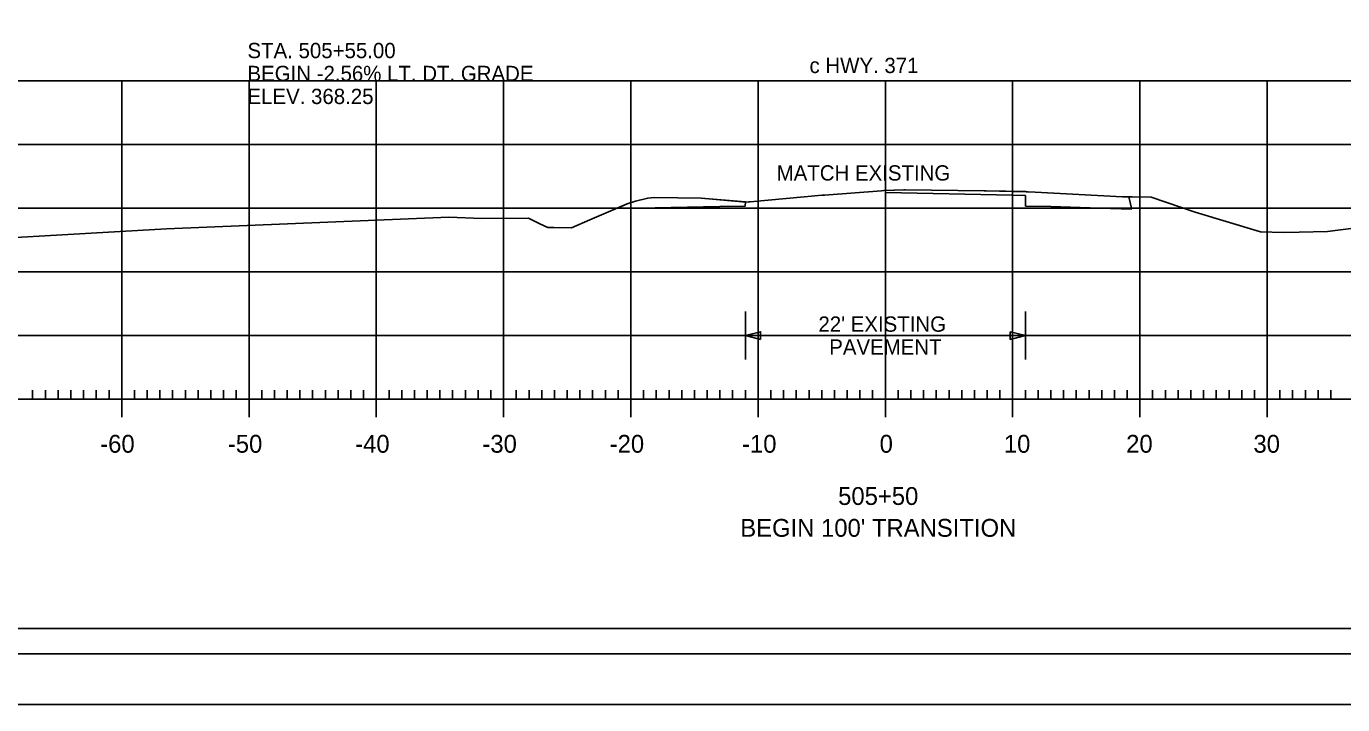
# Model space of a CAD drawing. Extents: x 1368910 to 1369601, y 380116 to 380950.
# Drawn here: x 1369012.7 to 1369116.2, y 380310.4 to 380363.7 of the extents above; entities that cross this region are included whole.
import ezdxf

# ---------------------------------------------------------------- set-up
doc = ezdxf.new("R2010")
doc.units = 0
for name, color, linetype in [('_STAGE 1 CUT', 7, 'Continuous'), ('_STAGE 2 FILL', 7, 'Continuous'), ('Notes', 7, 'Continuous'), ('R_Axis', 7, 'Continuous'), ('R_Axis Annot', 7, 'Continuous'), ('R_Border', 7, 'Continuous'), ('R_Exist Surface', 7, 'Continuous'), ('R_Grid', 7, 'Continuous'), ('R_No Plot', 7, 'Continuous'), ('R_ROW Annot', 7, 'Continuous')]:
    doc.layers.add(name, color=color, linetype=linetype)

msp = doc.modelspace()

# ---------------------------------------------------------------- linework, layer by layer
at = {"layer": '_STAGE 1 CUT'}
for q in [(1369080.24, 380350.81), (1369080.24, 380350.64)]:
    msp.add_line((1369080.24, 380350.81), q, dxfattribs=at)
for points in [[(1369099.36, 380350.31), (1369099.36, 380350.31), (1369098.86, 380350.3), (1369092.01, 380350.68), (1369091.46, 380350.71), (1369091.34, 380350.71), (1369091.26, 380350.72), (1369090.24, 380350.74), (1369088.16, 380350.79), (1369088, 380350.79), (1369081.79, 380350.85), (1369081.69, 380350.85), (1369080.24, 380350.81)], [(1369080.24, 380350.64), (1369090.24, 380350.44), (1369091.24, 380350.42)], [(1369091.24, 380350.42), (1369091.25, 380349.59), (1369093.24, 380349.55), (1369097.09, 380349.42), (1369099.61, 380349.34)], [(1369099.61, 380349.34), (1369099.58, 380349.42), (1369099.36, 380350.31)]]:
    msp.add_lwpolyline(points, dxfattribs=at)
at = {"layer": '_STAGE 2 FILL'}
for points in [[(1369069.24, 380349.91), (1369065.76, 380350.22), (1369062.09, 380350.27), (1369061.57, 380350.21), (1369060.61, 380349.97), (1369059.96, 380349.75), (1369059.19, 380349.42), (1369059.1, 380349.39)], [(1369059.1, 380349.39), (1369060.87, 380349.42), (1369067.24, 380349.55)], [(1369067.24, 380349.55), (1369069.23, 380349.59), (1369069.24, 380349.91)]]:
    msp.add_lwpolyline(points, dxfattribs=at)
at = {"layer": 'R_Axis'}
for p, q in [((1369020.24, 380333.02), (1369020.24, 380335.82)), ((1369030.24, 380333.02), (1369030.24, 380335.82)), ((1369040.24, 380333.02), (1369040.24, 380335.82)), ((1369050.24, 380333.02), (1369050.24, 380335.82)), ((1369060.24, 380333.02), (1369060.24, 380335.82)), ((1369070.24, 380333.02), (1369070.24, 380335.82)), ((1369080.24, 380333.02), (1369080.24, 380335.82)), ((1369090.24, 380333.02), (1369090.24, 380335.82)), ((1369100.24, 380333.02), (1369100.24, 380335.82)), ((1369110.24, 380333.02), (1369110.24, 380335.82)), ((1369013.24, 380334.42), (1369013.24, 380335.12)), ((1369014.24, 380334.42), (1369014.24, 380335.12)), ((1369015.24, 380334.42), (1369015.24, 380335.12)), ((1369016.24, 380334.42), (1369016.24, 380335.12)), ((1369017.24, 380334.42), (1369017.24, 380335.12)), ((1369018.24, 380334.42), (1369018.24, 380335.12)), ((1369019.24, 380334.42), (1369019.24, 380335.12)), ((1369021.24, 380334.42), (1369021.24, 380335.12)), ((1369022.24, 380334.42), (1369022.24, 380335.12)), ((1369023.24, 380334.42), (1369023.24, 380335.12)), ((1369024.24, 380334.42), (1369024.24, 380335.12)), ((1369025.24, 380334.42), (1369025.24, 380335.12)), ((1369026.24, 380334.42), (1369026.24, 380335.12)), ((1369027.24, 380334.42), (1369027.24, 380335.12)), ((1369028.24, 380334.42), (1369028.24, 380335.12)), ((1369029.24, 380334.42), (1369029.24, 380335.12)), ((1369031.24, 380334.42), (1369031.24, 380335.12)), ((1369032.24, 380334.42), (1369032.24, 380335.12)), ((1369033.24, 380334.42), (1369033.24, 380335.12)), ((1369034.24, 380334.42), (1369034.24, 380335.12)), ((1369035.24, 380334.42), (1369035.24, 380335.12)), ((1369036.24, 380334.42), (1369036.24, 380335.12)), ((1369037.24, 380334.42), (1369037.24, 380335.12)), ((1369038.24, 380334.42), (1369038.24, 380335.12)), ((1369039.24, 380334.42), (1369039.24, 380335.12)), ((1369041.24, 380334.42), (1369041.24, 380335.12)), ((1369042.24, 380334.42), (1369042.24, 380335.12)), ((1369043.24, 380334.42), (1369043.24, 380335.12)), ((1369044.24, 380334.42), (1369044.24, 380335.12)), ((1369045.24, 380334.42), (1369045.24, 380335.12)), ((1369046.24, 380334.42), (1369046.24, 380335.12)), ((1369047.24, 380334.42), (1369047.24, 380335.12)), ((1369048.24, 380334.42), (1369048.24, 380335.12)), ((1369049.24, 380334.42), (1369049.24, 380335.12)), ((1369051.24, 380334.42), (1369051.24, 380335.12)), ((1369052.24, 380334.42), (1369052.24, 380335.12)), ((1369053.24, 380334.42), (1369053.24, 380335.12)), ((1369054.24, 380334.42), (1369054.24, 380335.12)), ((1369055.24, 380334.42), (1369055.24, 380335.12)), ((1369056.24, 380334.42), (1369056.24, 380335.12)), ((1369057.24, 380334.42), (1369057.24, 380335.12)), ((1369058.24, 380334.42), (1369058.24, 380335.12)), ((1369059.24, 380334.42), (1369059.24, 380335.12)), ((1369061.24, 380334.42), (1369061.24, 380335.12)), ((1369062.24, 380334.42), (1369062.24, 380335.12)), ((1369063.24, 380334.42), (1369063.24, 380335.12)), ((1369064.24, 380334.42), (1369064.24, 380335.12)), ((1369065.24, 380334.42), (1369065.24, 380335.12)), ((1369066.24, 380334.42), (1369066.24, 380335.12)), ((1369067.24, 380334.42), (1369067.24, 380335.12)), ((1369068.24, 380334.42), (1369068.24, 380335.12)), ((1369069.24, 380334.42), (1369069.24, 380335.12)), ((1369071.24, 380334.42), (1369071.24, 380335.12)), ((1369072.24, 380334.42), (1369072.24, 380335.12)), ((1369073.24, 380334.42), (1369073.24, 380335.12)), ((1369074.24, 380334.42), (1369074.24, 380335.12)), ((1369075.24, 380334.42), (1369075.24, 380335.12)), ((1369076.24, 380334.42), (1369076.24, 380335.12)), ((1369077.24, 380334.42), (1369077.24, 380335.12)), ((1369078.24, 380334.42), (1369078.24, 380335.12)), ((1369079.24, 380334.42), (1369079.24, 380335.12)), ((1369081.24, 380334.42), (1369081.24, 380335.12)), ((1369082.24, 380334.42), (1369082.24, 380335.12)), ((1369083.24, 380334.42), (1369083.24, 380335.12)), ((1369084.24, 380334.42), (1369084.24, 380335.12)), ((1369085.24, 380334.42), (1369085.24, 380335.12)), ((1369086.24, 380334.42), (1369086.24, 380335.12)), ((1369087.24, 380334.42), (1369087.24, 380335.12)), ((1369088.24, 380334.42), (1369088.24, 380335.12)), ((1369089.24, 380334.42), (1369089.24, 380335.12)), ((1369091.24, 380334.42), (1369091.24, 380335.12)), ((1369092.24, 380334.42), (1369092.24, 380335.12)), ((1369093.24, 380334.42), (1369093.24, 380335.12)), ((1369094.24, 380334.42), (1369094.24, 380335.12)), ((1369095.24, 380334.42), (1369095.24, 380335.12)), ((1369096.24, 380334.42), (1369096.24, 380335.12)), ((1369097.24, 380334.42), (1369097.24, 380335.12)), ((1369098.24, 380334.42), (1369098.24, 380335.12)), ((1369099.24, 380334.42), (1369099.24, 380335.12)), ((1369101.24, 380334.42), (1369101.24, 380335.12)), ((1369102.24, 380334.42), (1369102.24, 380335.12)), ((1369103.24, 380334.42), (1369103.24, 380335.12)), ((1369104.24, 380334.42), (1369104.24, 380335.12)), ((1369105.24, 380334.42), (1369105.24, 380335.12)), ((1369106.24, 380334.42), (1369106.24, 380335.12)), ((1369107.24, 380334.42), (1369107.24, 380335.12)), ((1369108.24, 380334.42), (1369108.24, 380335.12)), ((1369109.24, 380334.42), (1369109.24, 380335.12)), ((1369111.24, 380334.42), (1369111.24, 380335.12)), ((1369112.24, 380334.42), (1369112.24, 380335.12)), ((1369113.24, 380334.42), (1369113.24, 380335.12)), ((1369114.24, 380334.42), (1369114.24, 380335.12)), ((1369115.24, 380334.42), (1369115.24, 380335.12)), ((1368940.24, 380334.42), (1369220.24, 380334.42))]:
    msp.add_line(p, q, dxfattribs=at)
at = {"layer": 'R_Border'}
msp.add_line((1369238.42, 380314.42), (1368922.24, 380314.42), dxfattribs=at)
at = {"layer": 'R_Exist Surface'}
msp.add_lwpolyline([(1369008.24, 380346.92), (1369023.75, 380347.79), (1369045.94, 380348.71), (1369048.54, 380348.61), (1369052.19, 380348.63), (1369053.1, 380348.19), (1369053.71, 380347.9), (1369054.2, 380347.91), (1369055.57, 380347.88), (1369057.01, 380348.5), (1369059.96, 380349.75), (1369060.61, 380349.97), (1369061.57, 380350.21), (1369062.09, 380350.27), (1369065.76, 380350.22), (1369069.29, 380349.9), (1369069.5, 380349.91), (1369069.53, 380349.91), (1369069.61, 380349.92), (1369075.27, 380350.44), (1369075.46, 380350.44), (1369079.93, 380350.79), (1369079.94, 380350.79), (1369080.13, 380350.8), (1369081.69, 380350.85), (1369081.79, 380350.85), (1369088, 380350.79), (1369088.16, 380350.79), (1369091.26, 380350.72), (1369091.34, 380350.71), (1369091.46, 380350.71), (1369092.01, 380350.68), (1369098.86, 380350.3), (1369099.63, 380350.31), (1369101.12, 380350.29), (1369104.58, 380349.1), (1369109.71, 380347.56), (1369111.51, 380347.5), (1369112.74, 380347.53), (1369114.99, 380347.6), (1369117.24, 380347.87)], dxfattribs=at)
at = {"layer": 'R_Grid'}
for p, q in [((1368940.24, 380359.42), (1369220.24, 380359.42)), ((1369020.24, 380334.42), (1369020.24, 380359.42)), ((1369030.24, 380334.42), (1369030.24, 380359.42)), ((1369040.24, 380334.42), (1369040.24, 380359.42)), ((1369050.24, 380334.42), (1369050.24, 380359.42)), ((1369060.24, 380334.42), (1369060.24, 380359.42)), ((1369070.24, 380334.42), (1369070.24, 380359.42)), ((1369080.24, 380334.42), (1369080.24, 380359.42)), ((1369090.24, 380334.42), (1369090.24, 380359.42)), ((1369100.24, 380334.42), (1369100.24, 380359.42)), ((1369110.24, 380334.42), (1369110.24, 380359.42)), ((1368940.24, 380354.42), (1369220.24, 380354.42)), ((1368940.24, 380349.42), (1369220.24, 380349.42)), ((1368940.24, 380344.42), (1369220.24, 380344.42)), ((1368940.24, 380339.42), (1369220.24, 380339.42)), ((1368940.24, 380334.42), (1369220.24, 380334.42))]:
    msp.add_line(p, q, dxfattribs=at)
at = {"layer": 'R_No Plot'}
for points in [[(1368909.84, 380523.78), (1369243.18, 380523.78), (1369243.18, 380310.44), (1368909.84, 380310.44)], [(1368924.24, 380517.88), (1369173.78, 380517.88), (1369173.78, 380508), (1369191.32, 380508), (1369215.42, 380508), (1369215.42, 380485.67), (1369236.42, 380485.67), (1369236.42, 380316.42), (1368924.24, 380316.42)], [(1368924.24, 380415.15), (1369236.42, 380415.15), (1369236.42, 380316.42), (1368924.24, 380316.42)]]:
    msp.add_lwpolyline(points, close=True, dxfattribs=at)
at = {"layer": 'R_ROW Annot'}
for p, q in [((1369069.24, 380337.54), (1369069.24, 380341.3)), ((1369091.24, 380337.54), (1369091.24, 380341.3)), ((1369091.24, 380339.42), (1369069.24, 380339.42))]:
    msp.add_line(p, q, dxfattribs=at)
for points in [[(1369070.44, 380339.12), (1369069.24, 380339.42), (1369070.44, 380339.72)], [(1369090.04, 380339.72), (1369091.24, 380339.42), (1369090.04, 380339.12)]]:
    msp.add_lwpolyline(points, close=True, dxfattribs=at)

# ---------------------------------------------------------------- texts
at = {"layer": 'Notes'}
for s, p in [('STA. 505+55.00', (1369030.12, 380361.2)), ('BEGIN -2.56% LT. DT. GRADE', (1369030.12, 380359.4)), ('c HWY. 371', (1369074.28, 380360.03)), ('ELEV. 368.25', (1369030.12, 380357.6)), ('MATCH EXISTING', (1369071.7, 380351.59))]:
    msp.add_text(s, height=1.2, dxfattribs=at).set_placement(p)
at = {"layer": 'R_Axis Annot'}
for s, p in [('-60', (1369018.55, 380330.22)), ('-50', (1369028.58, 380330.22)), ('-40', (1369038.58, 380330.22)), ('-30', (1369048.58, 380330.22)), ('-20', (1369058.58, 380330.22)), ('-10', (1369068.98, 380330.22)), ('0', (1369079.79, 380330.22)), ('10', (1369089.55, 380330.22)), ('20', (1369099.16, 380330.22)), ('30', (1369109.16, 380330.22)), ('505+50', (1369076.53, 380326.12)), ("BEGIN 100' TRANSITION", (1369068.84, 380323.62))]:
    msp.add_text(s, height=1.4, dxfattribs=at).set_placement(p)
at = {"layer": 'R_ROW Annot'}
for s, p in [("22' EXISTING", (1369074.98, 380339.72)), ('PAVEMENT', (1369075.83, 380337.92))]:
    msp.add_text(s, height=1.2, dxfattribs=at).set_placement(p)

doc.saveas('drawing.dxf')
